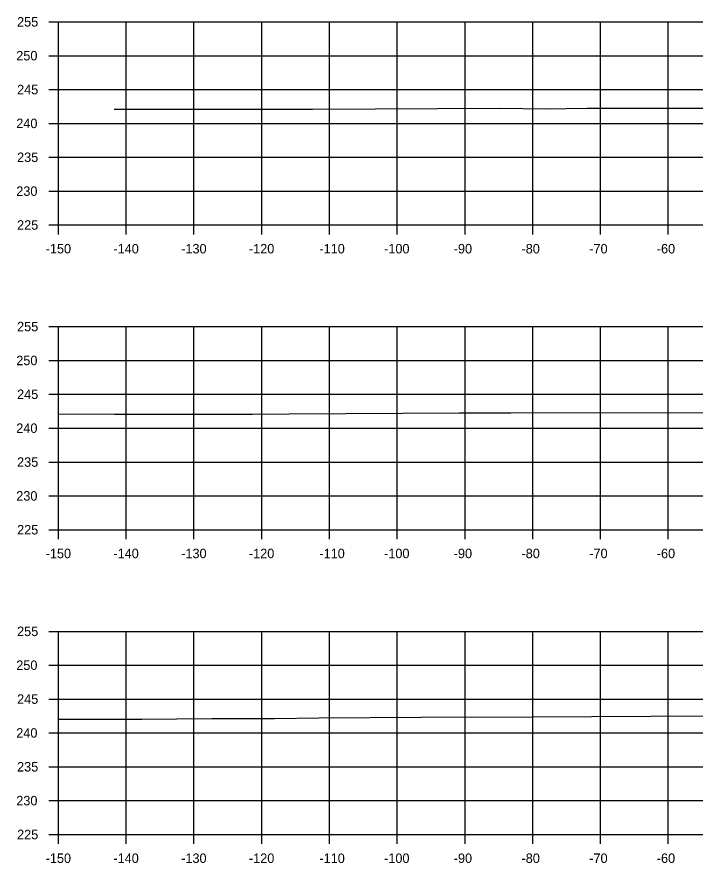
# Model space of a CAD drawing. Extents: x 1369627 to 1374022, y 380035 to 398173.
# Drawn here: x 1372730.1 to 1372830.2, y 383270.7 to 383395.6 of the extents above; entities that cross this region are included whole.
import ezdxf

# ---------------------------------------------------------------- set-up
doc = ezdxf.new("R2010")
doc.units = 0
for name, color, linetype in [('R_Axis', 7, 'Continuous'), ('R_Axis Annot', 7, 'Continuous'), ('R_Exist Surface', 7, 'Continuous'), ('R_Grid', 7, 'Continuous')]:
    doc.layers.add(name, color=color, linetype=linetype)

msp = doc.modelspace()

# ---------------------------------------------------------------- linework, layer by layer
at = {"layer": 'R_Axis'}
for p, q in [((1372734.81, 383394.91), (1372736.21, 383394.91)), ((1372736.21, 383364.91), (1372736.21, 383394.91)), ((1372734.81, 383389.91), (1372736.21, 383389.91)), ((1372734.81, 383384.91), (1372736.21, 383384.91)), ((1372734.81, 383379.91), (1372736.21, 383379.91)), ((1372734.81, 383374.91), (1372736.21, 383374.91)), ((1372734.81, 383369.91), (1372736.21, 383369.91)), ((1372734.81, 383364.91), (1372736.21, 383364.91)), ((1372736.21, 383364.91), (1373036.21, 383364.91)), ((1372736.21, 383363.51), (1372736.21, 383364.91)), ((1372746.21, 383363.51), (1372746.21, 383364.91)), ((1372756.21, 383363.51), (1372756.21, 383364.91)), ((1372766.21, 383363.51), (1372766.21, 383364.91)), ((1372776.21, 383363.51), (1372776.21, 383364.91)), ((1372786.21, 383363.51), (1372786.21, 383364.91)), ((1372796.21, 383363.51), (1372796.21, 383364.91)), ((1372806.21, 383363.51), (1372806.21, 383364.91)), ((1372816.21, 383363.51), (1372816.21, 383364.91)), ((1372826.21, 383363.51), (1372826.21, 383364.91)), ((1372734.81, 383349.91), (1372736.21, 383349.91)), ((1372736.21, 383319.91), (1372736.21, 383349.91)), ((1372734.81, 383344.91), (1372736.21, 383344.91)), ((1372734.81, 383339.91), (1372736.21, 383339.91)), ((1372734.81, 383334.91), (1372736.21, 383334.91)), ((1372734.81, 383329.91), (1372736.21, 383329.91)), ((1372734.81, 383324.91), (1372736.21, 383324.91)), ((1372734.81, 383319.91), (1372736.21, 383319.91)), ((1372736.21, 383319.91), (1373036.21, 383319.91)), ((1372736.21, 383318.51), (1372736.21, 383319.91)), ((1372746.21, 383318.51), (1372746.21, 383319.91)), ((1372756.21, 383318.51), (1372756.21, 383319.91)), ((1372766.21, 383318.51), (1372766.21, 383319.91)), ((1372776.21, 383318.51), (1372776.21, 383319.91)), ((1372786.21, 383318.51), (1372786.21, 383319.91)), ((1372796.21, 383318.51), (1372796.21, 383319.91)), ((1372806.21, 383318.51), (1372806.21, 383319.91)), ((1372816.21, 383318.51), (1372816.21, 383319.91)), ((1372826.21, 383318.51), (1372826.21, 383319.91)), ((1372734.81, 383304.91), (1372736.21, 383304.91)), ((1372736.21, 383274.91), (1372736.21, 383304.91)), ((1372734.81, 383299.91), (1372736.21, 383299.91)), ((1372734.81, 383294.91), (1372736.21, 383294.91)), ((1372734.81, 383289.91), (1372736.21, 383289.91)), ((1372734.81, 383284.91), (1372736.21, 383284.91)), ((1372734.81, 383279.91), (1372736.21, 383279.91)), ((1372734.81, 383274.91), (1372736.21, 383274.91)), ((1372736.21, 383274.91), (1373036.21, 383274.91)), ((1372736.21, 383273.51), (1372736.21, 383274.91)), ((1372746.21, 383273.51), (1372746.21, 383274.91)), ((1372756.21, 383273.51), (1372756.21, 383274.91)), ((1372766.21, 383273.51), (1372766.21, 383274.91)), ((1372776.21, 383273.51), (1372776.21, 383274.91)), ((1372786.21, 383273.51), (1372786.21, 383274.91)), ((1372796.21, 383273.51), (1372796.21, 383274.91)), ((1372806.21, 383273.51), (1372806.21, 383274.91)), ((1372816.21, 383273.51), (1372816.21, 383274.91)), ((1372826.21, 383273.51), (1372826.21, 383274.91))]:
    msp.add_line(p, q, dxfattribs=at)
at = {"layer": 'R_Exist Surface'}
for points in [[(1372744.43, 383382.02), (1372750.91, 383382), (1372768.8, 383382.01), (1372773.72, 383382.03), (1372801.42, 383382.16), (1372808.15, 383382.08), (1372814.2, 383382.16), (1372838.58, 383382.17)], [(1372736.21, 383337.01), (1372744.48, 383336.99), (1372761.88, 383337), (1372764.85, 383336.99), (1372770.24, 383337.04), (1372795.35, 383337.16), (1372802.95, 383337.19), (1372831.81, 383337.21)], [(1372736.21, 383291.96), (1372748.51, 383291.93), (1372758.85, 383292.02), (1372768.08, 383292.05), (1372774.66, 383292.15), (1372789.73, 383292.22), (1372806.2, 383292.28), (1372841.03, 383292.49)]]:
    msp.add_lwpolyline(points, dxfattribs=at)
at = {"layer": 'R_Grid'}
for p, q in [((1372736.21, 383394.91), (1373036.21, 383394.91)), ((1372736.21, 383364.91), (1372736.21, 383394.91)), ((1372746.21, 383364.91), (1372746.21, 383394.91)), ((1372756.21, 383364.91), (1372756.21, 383394.91)), ((1372766.21, 383364.91), (1372766.21, 383394.91)), ((1372776.21, 383364.91), (1372776.21, 383394.91)), ((1372786.21, 383364.91), (1372786.21, 383394.91)), ((1372796.21, 383364.91), (1372796.21, 383394.91)), ((1372806.21, 383364.91), (1372806.21, 383394.91)), ((1372816.21, 383364.91), (1372816.21, 383394.91)), ((1372826.21, 383364.91), (1372826.21, 383394.91)), ((1372736.21, 383389.91), (1373036.21, 383389.91)), ((1372736.21, 383384.91), (1373036.21, 383384.91)), ((1372736.21, 383379.91), (1373036.21, 383379.91)), ((1372736.21, 383374.91), (1373036.21, 383374.91)), ((1372736.21, 383369.91), (1373036.21, 383369.91)), ((1372736.21, 383364.91), (1373036.21, 383364.91)), ((1372736.21, 383349.91), (1373036.21, 383349.91)), ((1372736.21, 383319.91), (1372736.21, 383349.91)), ((1372746.21, 383319.91), (1372746.21, 383349.91)), ((1372756.21, 383319.91), (1372756.21, 383349.91)), ((1372766.21, 383319.91), (1372766.21, 383349.91)), ((1372776.21, 383319.91), (1372776.21, 383349.91)), ((1372786.21, 383319.91), (1372786.21, 383349.91)), ((1372796.21, 383319.91), (1372796.21, 383349.91)), ((1372806.21, 383319.91), (1372806.21, 383349.91)), ((1372816.21, 383319.91), (1372816.21, 383349.91)), ((1372826.21, 383319.91), (1372826.21, 383349.91)), ((1372736.21, 383344.91), (1373036.21, 383344.91)), ((1372736.21, 383339.91), (1373036.21, 383339.91)), ((1372736.21, 383334.91), (1373036.21, 383334.91)), ((1372736.21, 383329.91), (1373036.21, 383329.91)), ((1372736.21, 383324.91), (1373036.21, 383324.91)), ((1372736.21, 383319.91), (1373036.21, 383319.91)), ((1372736.21, 383304.91), (1373036.21, 383304.91)), ((1372736.21, 383274.91), (1372736.21, 383304.91)), ((1372746.21, 383274.91), (1372746.21, 383304.91)), ((1372756.21, 383274.91), (1372756.21, 383304.91)), ((1372766.21, 383274.91), (1372766.21, 383304.91)), ((1372776.21, 383274.91), (1372776.21, 383304.91)), ((1372786.21, 383274.91), (1372786.21, 383304.91)), ((1372796.21, 383274.91), (1372796.21, 383304.91)), ((1372806.21, 383274.91), (1372806.21, 383304.91)), ((1372816.21, 383274.91), (1372816.21, 383304.91)), ((1372826.21, 383274.91), (1372826.21, 383304.91)), ((1372736.21, 383299.91), (1373036.21, 383299.91)), ((1372736.21, 383294.91), (1373036.21, 383294.91)), ((1372736.21, 383289.91), (1373036.21, 383289.91)), ((1372736.21, 383284.91), (1373036.21, 383284.91)), ((1372736.21, 383279.91), (1373036.21, 383279.91)), ((1372736.21, 383274.91), (1373036.21, 383274.91))]:
    msp.add_line(p, q, dxfattribs=at)

# ---------------------------------------------------------------- texts
at = {"layer": 'R_Axis Annot'}
for s, p in [('255', (1372730.1, 383394.21)), ('250', (1372729.98, 383389.21)), ('245', (1372730.1, 383384.21)), ('240', (1372729.98, 383379.21)), ('235', (1372730.1, 383374.21)), ('230', (1372729.98, 383369.21)), ('225', (1372730.1, 383364.21)), ('-150', (1372734.32, 383360.71)), ('-140', (1372744.32, 383360.71)), ('-130', (1372754.32, 383360.71)), ('-120', (1372764.32, 383360.71)), ('-110', (1372774.72, 383360.71)), ('-100', (1372784.27, 383360.71)), ('-90', (1372794.55, 383360.71)), ('-80', (1372804.55, 383360.71)), ('-70', (1372814.55, 383360.71)), ('-60', (1372824.52, 383360.71)), ('255', (1372730.1, 383349.21)), ('250', (1372729.98, 383344.21)), ('245', (1372730.1, 383339.21)), ('240', (1372729.98, 383334.21)), ('235', (1372730.1, 383329.21)), ('230', (1372729.98, 383324.21)), ('225', (1372730.1, 383319.21)), ('-150', (1372734.32, 383315.71)), ('-140', (1372744.32, 383315.71)), ('-130', (1372754.32, 383315.71)), ('-120', (1372764.32, 383315.71)), ('-110', (1372774.72, 383315.71)), ('-100', (1372784.27, 383315.71)), ('-90', (1372794.55, 383315.71)), ('-80', (1372804.55, 383315.71)), ('-70', (1372814.55, 383315.71)), ('-60', (1372824.52, 383315.71)), ('255', (1372730.1, 383304.21)), ('250', (1372729.98, 383299.21)), ('245', (1372730.1, 383294.21)), ('240', (1372729.98, 383289.21)), ('235', (1372730.1, 383284.21)), ('230', (1372729.98, 383279.21)), ('225', (1372730.1, 383274.21)), ('-150', (1372734.32, 383270.71)), ('-140', (1372744.32, 383270.71)), ('-130', (1372754.32, 383270.71)), ('-120', (1372764.32, 383270.71)), ('-110', (1372774.72, 383270.71)), ('-100', (1372784.27, 383270.71)), ('-90', (1372794.55, 383270.71)), ('-80', (1372804.55, 383270.71)), ('-70', (1372814.55, 383270.71)), ('-60', (1372824.52, 383270.71))]:
    msp.add_text(s, height=1.4, dxfattribs=at).set_placement(p)

doc.saveas('drawing.dxf')
